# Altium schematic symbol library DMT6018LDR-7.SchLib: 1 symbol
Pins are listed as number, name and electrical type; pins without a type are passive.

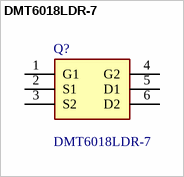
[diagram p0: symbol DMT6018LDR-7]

## DMT6018LDR-7
designator Q?
DIODES INC. - DMT6018LDR-7 - Dual MOSFET, N Channel, 60 V, 60 V, 8.8 A, 8.8 A, 0.013 ohm; Manufacturer_Name: Diodes Incorporated; Geometry.Height: 0.85mm
footprint DMT6018LDR7
pins: 1 G1, 2 S1, 3 S2, 4 G2, 5 D1, 6 D2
